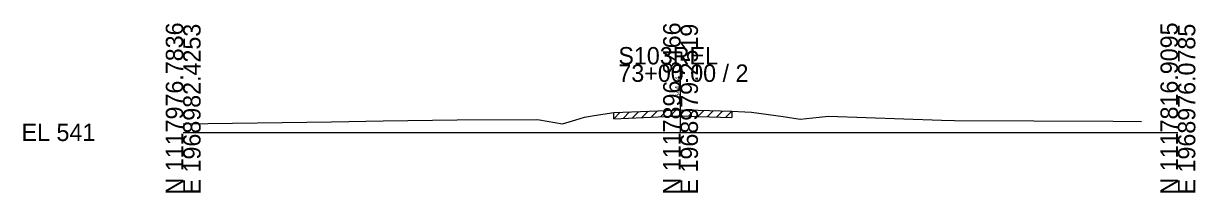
# Model space of a CAD drawing. Extents: x -26 to 163, y -10 to 24518.
# Drawn here: x -25.7 to 162.8, y 21490.3 to 21517.5 of the extents above; entities that cross this region are included whole.
import ezdxf

# ---------------------------------------------------------------- set-up
doc = ezdxf.new("R2010")
doc.units = 0
for name, color, linetype in [('RD_GPK_XS_Cell', 7, 'Continuous'), ('RD_XS_ExGround', 7, 'Continuous'), ('RD_XS_ExPaveRet', 7, 'Continuous'), ('RD_XS_TX_Elev_EX', 7, 'Continuous')]:
    doc.layers.add(name, color=color, linetype=linetype)

msp = doc.modelspace()

# ---------------------------------------------------------------- linework, layer by layer
at = {"layer": 'RD_GPK_XS_Cell'}
for p, q in [((80, 21500), (80, 21510.93)), ((0, 21500), (80, 21500)), ((80, 21500), (160, 21500))]:
    msp.add_line(p, q, dxfattribs=at)
at = {"layer": 'RD_XS_ExGround'}
msp.add_lwpolyline([(0, 21501.37), (23.84, 21501.68), (32.19, 21501.85), (44.07, 21502), (56.87, 21502.06), (57.32, 21501.99), (61.01, 21501.38), (63.14, 21502.03), (64.57, 21502.45), (66.11, 21502.69), (69.26, 21503.19), (76.42, 21503.49), (80.06, 21503.64), (82.83, 21503.55), (88.27, 21503.39), (90.33, 21503.32), (91.43, 21503.27), (96.53, 21502.53), (99.25, 21502.13), (102.29, 21502.44), (103.8, 21502.6), (121.99, 21501.98), (124.04, 21501.92), (149.6, 21501.8), (154.17, 21501.73)], dxfattribs=at)
at = {"layer": 'RD_XS_ExPaveRet'}
for p, q in [((69.26, 21502.19), (70.3, 21503.23)), ((69.26, 21502.19), (69.26, 21503.19)), ((69.26, 21502.19), (76.42, 21502.49)), ((70.76, 21502.25), (71.8, 21503.3)), ((72.26, 21502.32), (73.3, 21503.36)), ((73.76, 21502.38), (74.8, 21503.43)), ((75.26, 21502.45), (76.3, 21503.49)), ((76.42, 21502.49), (80.06, 21502.64)), ((76.76, 21502.51), (77.8, 21503.55)), ((78.26, 21502.57), (79.3, 21503.61)), ((79.76, 21502.63), (80.75, 21503.62)), ((80.06, 21502.64), (82.83, 21502.55)), ((81.26, 21502.61), (82.23, 21503.57)), ((82.76, 21502.56), (83.73, 21503.53)), ((82.83, 21502.55), (88.27, 21502.39)), ((84.26, 21502.51), (85.23, 21503.48)), ((85.76, 21502.46), (86.73, 21503.43)), ((87.26, 21502.42), (88.23, 21503.39)), ((88.27, 21503.39), (88.27, 21502.39))]:
    msp.add_line(p, q, dxfattribs=at)

# ---------------------------------------------------------------- texts
at = {"layer": 'RD_GPK_XS_Cell'}
for s, p in [('N 1117976.7836', (0, 21490)), ('E 1968982.4253', (2.8, 21490)), ('N 1117896.8466', (80, 21490)), ('E 1968979.2519', (82.8, 21490)), ('N 1117816.9095', (160, 21490)), ('E 1968976.0785', (162.8, 21490))]:
    msp.add_text(s, height=2.8, rotation=90, dxfattribs=at).set_placement(p)
for s, p in [('S103REL', (70, 21510.93)), ('73+00.00 / 2', (70, 21508.13)), ('EL 541', (-26, 21498.6))]:
    msp.add_text(s, height=2.8, dxfattribs=at).set_placement(p)
at = {"layer": 'RD_XS_TX_Elev_EX'}
msp.add_text('544.64', height=0.8, rotation=90, dxfattribs=at).set_placement((79.9, 21505.64))

doc.saveas('drawing.dxf')
